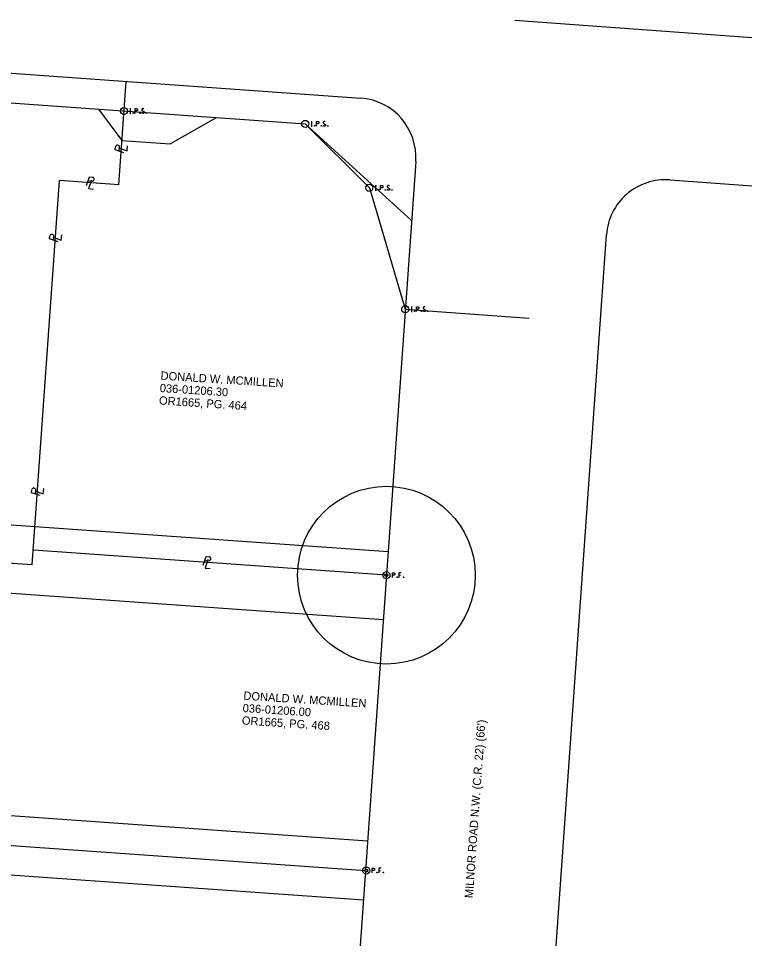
# Model space of a CAD drawing. Extents: x 1898254 to 1901377, y 701554 to 704886.
# Drawn here: x 1899648.1 to 1899893.4, y 702919.7 to 703230.4 of the extents above; entities that cross this region are included whole.
import ezdxf

# ---------------------------------------------------------------- set-up
doc = ezdxf.new("R2010")
doc.units = 0
for name, color, linetype in [('_CIVIL_CONSTRUCTION', 7, 'Continuous'), ('DV_X_Property_Line', 7, 'Continuous'), ('DV_X_Text', 7, 'Continuous'), ('PF_X_Ground_Line', 7, 'Continuous'), ('RW_X_CL', 7, 'Continuous'), ('RW_X_Esmt_SW', 7, 'Continuous'), ('RW_X_Esmt_U', 7, 'Continuous'), ('RW_X_Fee_RW', 7, 'Continuous'), ('RW_X_Text', 7, 'Continuous'), ('SC_Scratch1', 7, 'Continuous'), ('SC_Scratch2', 7, 'Continuous'), ('SC_Scratch5', 7, 'Continuous'), ('SG_X_Manhole', 7, 'Continuous'), ('SV_P_Mon_Cells_Set', 7, 'Continuous'), ('SV_X_Mon_Cells_Found', 7, 'Continuous')]:
    doc.layers.add(name, color=color, linetype=linetype)

msp = doc.modelspace()

# ---------------------------------------------------------------- linework, layer by layer
at = {"layer": '_CIVIL_CONSTRUCTION'}
msp.add_lwpolyline([(1899675.17, 703199.74), (1899683.04, 703189.15), (1899699.4, 703187.99), (1899715.07, 703196.9)], dxfattribs=at)
at = {"layer": 'DV_X_Property_Line'}
for p, q in [((1899681.98, 703174.19), (1899684.46, 703209.1)), ((1899682.16, 703185.57), (1899682.25, 703186.87)), ((1899682.84, 703186.33), (1899682.84, 703186.33)), ((1899652.8, 703045.9), (1899662.03, 703175.61)), ((1899681.98, 703174.19), (1899662.03, 703175.61)), ((1899671.67, 703175.55), (1899672.96, 703175.45)), ((1899672.42, 703174.87), (1899672.42, 703174.87)), ((1899659.97, 703155.46), (1899660.06, 703156.75)), ((1899660.65, 703156.21), (1899660.65, 703156.21)), ((1899653.88, 703069.79), (1899653.97, 703071.08)), ((1899654.56, 703070.54), (1899654.56, 703070.54)), ((1899652.8, 703045.9), (1899563.03, 703052.28)), ((1899772.41, 703042.41), (1899653.16, 703050.89)), ((1899711.05, 703047.39), (1899712.34, 703047.3)), ((1899711.8, 703046.72), (1899711.8, 703046.72)), ((1899466.52, 702963.89), (1899765.35, 702942.72))]:
    msp.add_line(p, q, dxfattribs=at)
for points in [[(1899683.72, 703185.04), (1899680.82, 703186.03), (1899680.89, 703187.06)], [(1899681.9, 703186.66), (1899684.8, 703185.66), (1899684.92, 703187.41)], [(1899671.13, 703173.99), (1899672.12, 703176.89), (1899673.16, 703176.82)], [(1899672.76, 703175.81), (1899671.76, 703172.91), (1899673.5, 703172.79)], [(1899661.53, 703154.93), (1899658.63, 703155.92), (1899658.7, 703156.95)], [(1899659.71, 703156.55), (1899662.6, 703155.55), (1899662.73, 703157.29)], [(1899655.44, 703069.26), (1899652.53, 703070.25), (1899652.61, 703071.28)], [(1899653.62, 703070.88), (1899656.51, 703069.88), (1899656.64, 703071.62)], [(1899710.51, 703045.84), (1899711.5, 703048.74), (1899712.53, 703048.66)], [(1899712.14, 703047.65), (1899711.14, 703044.76), (1899712.88, 703044.64)]]:
    msp.add_lwpolyline(points, dxfattribs=at)
for centre, start, end in [((1899681.57, 703186.91), 356.4035, 167.2606), ((1899673, 703176.14), 266.4035, 77.2606), ((1899659.37, 703156.8), 356.4035, 167.2606), ((1899653.28, 703071.13), 356.4035, 167.2606), ((1899712.38, 703047.99), 266.4035, 77.2606)]:
    msp.add_arc(centre, 0.69, start, end, dxfattribs=at)
at = {"layer": 'DV_X_Text'}
msp.add_line((1899778.77, 703132.21), (1899820.67, 703129.24), dxfattribs=at)
at = {"layer": 'PF_X_Ground_Line'}
msp.add_lwpolyline([(1899484.96, 703223.29), (1899484.25, 703213.31), (1899745, 703194.77), (1899766.64, 703173.17), (1899778.77, 703132.21)], dxfattribs=at)
at = {"layer": 'RW_X_CL'}
msp.add_line((1899815.76, 703229.84), (1901162.17, 703131.42), dxfattribs=at)
at = {"layer": 'RW_X_Esmt_SW'}
for p, q in [((1899489.14, 703070.57), (1899772.98, 703050.39)), ((1899492.79, 703047.25), (1899771.35, 703027.44))]:
    msp.add_line(p, q, dxfattribs=at)
at = {"layer": 'RW_X_Esmt_U'}
for points in [[(1899494.94, 703222.58), (1899477.2, 702973.16), (1899766.06, 702952.7)], [(1899550.18, 702947.94), (1899580.04, 702945.82), (1899764.64, 702932.75)]]:
    msp.add_lwpolyline(points, dxfattribs=at)
at = {"layer": 'RW_X_Fee_RW'}
for p, q in [((1898449.4, 703296.93), (1899763.77, 703203.46)), ((1899782.31, 703182.1), (1899756.17, 702813.12)), ((1899868.13, 703175.88), (1900606.62, 703121.9)), ((1899745.58, 701729.7), (1899846.72, 703157.34))]:
    msp.add_line(p, q, dxfattribs=at)
for centre, start, end in [((1899762.36, 703183.51), 355.9478, 85.9325), ((1899866.67, 703155.93), 85.8192, 175.9478)]:
    msp.add_arc(centre, 20, start, end, dxfattribs=at)
at = {"layer": 'SC_Scratch1'}
msp.add_circle((1899772.41, 703042.41), 30, dxfattribs=at)
at = {"layer": 'SC_Scratch2'}
msp.add_circle((1899815.76, 703229.84), 1561.35, dxfattribs=at)
at = {"layer": 'SC_Scratch5'}
for p, q in [((1898449.4, 703296.93), (1899763.77, 703203.46)), ((1899782.31, 703182.1), (1899700.34, 702025)), ((1899868.13, 703175.88), (1900606.62, 703121.9)), ((1899745.58, 701729.7), (1899846.72, 703157.34))]:
    msp.add_line(p, q, dxfattribs=at)
for points in [[(1899484.96, 703223.29), (1899484.25, 703213.31), (1899745, 703194.77), (1899780.89, 703162.13)], [(1899675.17, 703199.74), (1899683.04, 703189.15), (1899699.4, 703187.99), (1899715.07, 703196.9)]]:
    msp.add_lwpolyline(points, dxfattribs=at)
for centre, start, end in [((1899762.36, 703183.51), 355.9478, 85.9325), ((1899866.67, 703155.93), 85.8192, 175.9478)]:
    msp.add_arc(centre, 20, start, end, dxfattribs=at)
at = {"layer": 'SG_X_Manhole'}
for points in [[(1899484.96, 703223.29), (1899484.25, 703213.31), (1899745, 703194.77), (1899780.89, 703162.13)], [(1899484.96, 703223.29), (1899484.25, 703213.31), (1899745, 703194.77), (1899745, 703194.77)]]:
    msp.add_lwpolyline(points, dxfattribs=at)
at = {"layer": 'SV_P_Mon_Cells_Set'}
for points in [[(1899685.77, 703199.93), (1899686.12, 703199.93)], [(1899685.77, 703198.33), (1899686.12, 703198.33)], [(1899685.95, 703198.33), (1899685.95, 703199.93)], [(1899686.91, 703198.54), (1899686.96, 703198.54), (1899686.99, 703198.52), (1899687.03, 703198.47), (1899687.03, 703198.4), (1899686.99, 703198.35), (1899686.96, 703198.33), (1899686.91, 703198.33), (1899686.87, 703198.35), (1899686.84, 703198.4), (1899686.84, 703198.47), (1899686.87, 703198.52), (1899686.91, 703198.54)], [(1899687.51, 703198.33), (1899687.51, 703199.93), (1899688.04, 703199.93), (1899688.1, 703199.91), (1899688.17, 703199.89), (1899688.21, 703199.86), (1899688.24, 703199.84), (1899688.28, 703199.78), (1899688.32, 703199.71), (1899688.34, 703199.61), (1899688.34, 703199.46), (1899688.33, 703199.41), (1899688.31, 703199.33), (1899688.26, 703199.25), (1899688.22, 703199.21), (1899688.18, 703199.18), (1899688.13, 703199.16), (1899688.04, 703199.15), (1899687.51, 703199.15)], [(1899689.15, 703198.54), (1899689.21, 703198.54), (1899689.24, 703198.52), (1899689.28, 703198.47), (1899689.28, 703198.4), (1899689.24, 703198.35), (1899689.21, 703198.33), (1899689.15, 703198.33), (1899689.12, 703198.35), (1899689.09, 703198.4), (1899689.09, 703198.47), (1899689.12, 703198.52), (1899689.15, 703198.54)], [(1899690.52, 703199.81), (1899690.5, 703199.84), (1899690.47, 703199.86), (1899690.37, 703199.9), (1899690.25, 703199.93), (1899690.16, 703199.93), (1899690.12, 703199.93), (1899689.98, 703199.89), (1899689.86, 703199.81), (1899689.78, 703199.71), (1899689.76, 703199.61), (1899689.76, 703199.54), (1899689.78, 703199.44), (1899689.87, 703199.35), (1899690.48, 703198.97), (1899690.53, 703198.92), (1899690.55, 703198.87), (1899690.58, 703198.79), (1899690.58, 703198.72), (1899690.56, 703198.64), (1899690.55, 703198.59), (1899690.53, 703198.53), (1899690.51, 703198.48), (1899690.49, 703198.44), (1899690.45, 703198.4), (1899690.42, 703198.38), (1899690.38, 703198.35), (1899690.34, 703198.34), (1899690.25, 703198.33), (1899690.09, 703198.33), (1899689.99, 703198.35), (1899689.85, 703198.44), (1899689.76, 703198.52)], [(1899691.34, 703198.54), (1899691.39, 703198.54), (1899691.42, 703198.52), (1899691.46, 703198.47), (1899691.46, 703198.4), (1899691.42, 703198.35), (1899691.39, 703198.33), (1899691.34, 703198.33), (1899691.3, 703198.35), (1899691.27, 703198.4), (1899691.27, 703198.47), (1899691.3, 703198.52), (1899691.34, 703198.54)], [(1899747.01, 703195.57), (1899747.37, 703195.57)], [(1899747.19, 703193.97), (1899747.19, 703195.57)], [(1899748.76, 703193.97), (1899748.76, 703195.57), (1899749.28, 703195.57), (1899749.34, 703195.56), (1899749.42, 703195.53), (1899749.45, 703195.51), (1899749.48, 703195.48), (1899749.53, 703195.42), (1899749.56, 703195.36), (1899749.58, 703195.26), (1899749.58, 703195.11), (1899749.57, 703195.06), (1899749.55, 703194.98), (1899749.51, 703194.89), (1899749.46, 703194.85), (1899749.43, 703194.83), (1899749.37, 703194.8), (1899749.28, 703194.79), (1899748.76, 703194.79)], [(1899751.77, 703195.46), (1899751.74, 703195.48), (1899751.71, 703195.51), (1899751.61, 703195.55), (1899751.49, 703195.57), (1899751.4, 703195.57), (1899751.37, 703195.57), (1899751.22, 703195.53), (1899751.1, 703195.46), (1899751.03, 703195.36), (1899751, 703195.26), (1899751, 703195.18), (1899751.03, 703195.08), (1899751.11, 703194.99), (1899751.72, 703194.61), (1899751.78, 703194.56), (1899751.8, 703194.51), (1899751.82, 703194.44), (1899751.82, 703194.36), (1899751.81, 703194.29), (1899751.8, 703194.24), (1899751.78, 703194.17), (1899751.75, 703194.12), (1899751.73, 703194.09), (1899751.7, 703194.05), (1899751.67, 703194.02), (1899751.62, 703194), (1899751.59, 703193.98), (1899751.49, 703193.97), (1899751.34, 703193.97), (1899751.24, 703194), (1899751.09, 703194.09), (1899751, 703194.16)], [(1899747.01, 703193.97), (1899747.37, 703193.97)], [(1899748.15, 703194.19), (1899748.2, 703194.19), (1899748.24, 703194.16), (1899748.27, 703194.11), (1899748.27, 703194.05), (1899748.24, 703194), (1899748.2, 703193.97), (1899748.15, 703193.97), (1899748.12, 703194), (1899748.08, 703194.05), (1899748.08, 703194.11), (1899748.12, 703194.16), (1899748.15, 703194.19)], [(1899750.4, 703194.19), (1899750.45, 703194.19), (1899750.49, 703194.16), (1899750.52, 703194.11), (1899750.52, 703194.05), (1899750.49, 703194), (1899750.45, 703193.97), (1899750.4, 703193.97), (1899750.37, 703194), (1899750.33, 703194.05), (1899750.33, 703194.11), (1899750.37, 703194.16), (1899750.4, 703194.19)], [(1899752.58, 703194.19), (1899752.64, 703194.19), (1899752.67, 703194.16), (1899752.7, 703194.11), (1899752.7, 703194.05), (1899752.67, 703194), (1899752.64, 703193.97), (1899752.58, 703193.97), (1899752.55, 703194), (1899752.51, 703194.05), (1899752.51, 703194.11), (1899752.55, 703194.16), (1899752.58, 703194.19)], [(1899768.66, 703173.97), (1899769.01, 703173.97)], [(1899768.83, 703172.37), (1899768.83, 703173.97)], [(1899770.4, 703172.37), (1899770.4, 703173.97), (1899770.93, 703173.97), (1899770.98, 703173.96), (1899771.06, 703173.93), (1899771.09, 703173.91), (1899771.12, 703173.88), (1899771.17, 703173.82), (1899771.2, 703173.76), (1899771.22, 703173.66), (1899771.22, 703173.5), (1899771.21, 703173.45), (1899771.19, 703173.38), (1899771.15, 703173.29), (1899771.1, 703173.25), (1899771.07, 703173.23), (1899771.01, 703173.2), (1899770.93, 703173.19), (1899770.4, 703173.19)], [(1899773.41, 703173.86), (1899773.38, 703173.88), (1899773.35, 703173.91), (1899773.25, 703173.95), (1899773.13, 703173.97), (1899773.04, 703173.97), (1899773.01, 703173.97), (1899772.87, 703173.93), (1899772.75, 703173.86), (1899772.67, 703173.76), (1899772.65, 703173.66), (1899772.65, 703173.58), (1899772.67, 703173.48), (1899772.76, 703173.39), (1899773.36, 703173.01), (1899773.42, 703172.96), (1899773.44, 703172.91), (1899773.46, 703172.84), (1899773.46, 703172.76), (1899773.45, 703172.69), (1899773.44, 703172.64), (1899773.42, 703172.57), (1899773.4, 703172.52), (1899773.37, 703172.48), (1899773.34, 703172.45), (1899773.31, 703172.42), (1899773.26, 703172.4), (1899773.23, 703172.38), (1899773.13, 703172.37), (1899772.98, 703172.37), (1899772.88, 703172.4), (1899772.73, 703172.48), (1899772.65, 703172.56)], [(1899768.66, 703172.37), (1899769.01, 703172.37)], [(1899769.79, 703172.58), (1899769.85, 703172.58), (1899769.88, 703172.56), (1899769.91, 703172.51), (1899769.91, 703172.45), (1899769.88, 703172.4), (1899769.85, 703172.37), (1899769.79, 703172.37), (1899769.76, 703172.4), (1899769.72, 703172.45), (1899769.72, 703172.51), (1899769.76, 703172.56), (1899769.79, 703172.58)], [(1899772.04, 703172.58), (1899772.09, 703172.58), (1899772.13, 703172.56), (1899772.16, 703172.51), (1899772.16, 703172.45), (1899772.13, 703172.4), (1899772.09, 703172.37), (1899772.04, 703172.37), (1899772.01, 703172.4), (1899771.97, 703172.45), (1899771.97, 703172.51), (1899772.01, 703172.56), (1899772.04, 703172.58)], [(1899774.22, 703172.58), (1899774.28, 703172.58), (1899774.31, 703172.56), (1899774.34, 703172.51), (1899774.34, 703172.45), (1899774.31, 703172.4), (1899774.28, 703172.37), (1899774.22, 703172.37), (1899774.19, 703172.4), (1899774.16, 703172.45), (1899774.16, 703172.51), (1899774.19, 703172.56), (1899774.22, 703172.58)], [(1899780.79, 703133.01), (1899781.14, 703133.01)], [(1899780.97, 703131.41), (1899780.97, 703133.01)], [(1899782.53, 703131.41), (1899782.53, 703133.01), (1899783.06, 703133.01), (1899783.12, 703133), (1899783.19, 703132.97), (1899783.23, 703132.95), (1899783.26, 703132.92), (1899783.3, 703132.86), (1899783.34, 703132.8), (1899783.36, 703132.7), (1899783.36, 703132.54), (1899783.35, 703132.49), (1899783.33, 703132.42), (1899783.28, 703132.33), (1899783.24, 703132.29), (1899783.21, 703132.27), (1899783.15, 703132.24), (1899783.06, 703132.23), (1899782.53, 703132.23)], [(1899785.54, 703132.9), (1899785.52, 703132.92), (1899785.49, 703132.95), (1899785.39, 703132.99), (1899785.27, 703133.01), (1899785.18, 703133.01), (1899785.15, 703133.01), (1899785, 703132.97), (1899784.88, 703132.9), (1899784.8, 703132.8), (1899784.78, 703132.7), (1899784.78, 703132.62), (1899784.8, 703132.52), (1899784.89, 703132.43), (1899785.5, 703132.05), (1899785.55, 703132), (1899785.57, 703131.95), (1899785.6, 703131.88), (1899785.6, 703131.8), (1899785.59, 703131.73), (1899785.57, 703131.68), (1899785.55, 703131.61), (1899785.53, 703131.56), (1899785.51, 703131.52), (1899785.48, 703131.49), (1899785.44, 703131.46), (1899785.4, 703131.44), (1899785.37, 703131.42), (1899785.27, 703131.41), (1899785.11, 703131.41), (1899785.01, 703131.44), (1899784.87, 703131.52), (1899784.78, 703131.6)], [(1899780.79, 703131.41), (1899781.14, 703131.41)], [(1899781.93, 703131.62), (1899781.98, 703131.62), (1899782.01, 703131.6), (1899782.05, 703131.55), (1899782.05, 703131.49), (1899782.01, 703131.44), (1899781.98, 703131.41), (1899781.93, 703131.41), (1899781.89, 703131.44), (1899781.86, 703131.49), (1899781.86, 703131.55), (1899781.89, 703131.6), (1899781.93, 703131.62)], [(1899784.18, 703131.62), (1899784.23, 703131.62), (1899784.26, 703131.6), (1899784.3, 703131.55), (1899784.3, 703131.49), (1899784.26, 703131.44), (1899784.23, 703131.41), (1899784.18, 703131.41), (1899784.14, 703131.44), (1899784.11, 703131.49), (1899784.11, 703131.55), (1899784.14, 703131.6), (1899784.18, 703131.62)], [(1899786.36, 703131.62), (1899786.41, 703131.62), (1899786.45, 703131.6), (1899786.48, 703131.55), (1899786.48, 703131.49), (1899786.45, 703131.44), (1899786.41, 703131.41), (1899786.36, 703131.41), (1899786.32, 703131.44), (1899786.29, 703131.49), (1899786.29, 703131.55), (1899786.32, 703131.6), (1899786.36, 703131.62)]]:
    msp.add_lwpolyline(points, dxfattribs=at)
for centre in [(1899683.75, 703199.13), (1899745, 703194.77), (1899766.64, 703173.17), (1899778.77, 703132.21)]:
    msp.add_circle(centre, 1.2, dxfattribs=at)
at = {"layer": 'SV_X_Mon_Cells_Found'}
for points in [[(1899774.41, 703041.61), (1899774.41, 703043.21), (1899774.94, 703043.21), (1899774.99, 703043.19), (1899775.07, 703043.17), (1899775.1, 703043.14), (1899775.13, 703043.12), (1899775.18, 703043.05), (1899775.21, 703042.99), (1899775.23, 703042.89), (1899775.23, 703042.74), (1899775.22, 703042.69), (1899775.2, 703042.61), (1899775.16, 703042.53), (1899775.11, 703042.49), (1899775.08, 703042.46), (1899775.02, 703042.44), (1899774.94, 703042.42), (1899774.41, 703042.42)], [(1899777.42, 703043.21), (1899776.66, 703043.21), (1899776.66, 703041.61)], [(1899776.05, 703041.82), (1899776.1, 703041.82), (1899776.14, 703041.8), (1899776.17, 703041.74), (1899776.17, 703041.68), (1899776.14, 703041.63), (1899776.1, 703041.61), (1899776.05, 703041.61), (1899776.02, 703041.63), (1899775.98, 703041.68), (1899775.98, 703041.74), (1899776.02, 703041.8), (1899776.05, 703041.82)], [(1899776.66, 703042.42), (1899777.2, 703042.42)], [(1899778.2, 703041.82), (1899778.25, 703041.82), (1899778.29, 703041.8), (1899778.32, 703041.74), (1899778.32, 703041.68), (1899778.29, 703041.63), (1899778.25, 703041.61), (1899778.2, 703041.61), (1899778.17, 703041.63), (1899778.13, 703041.68), (1899778.13, 703041.74), (1899778.17, 703041.8), (1899778.2, 703041.82)], [(1899767.59, 702941.91), (1899767.59, 702943.51), (1899768.12, 702943.51), (1899768.18, 702943.49), (1899768.25, 702943.47), (1899768.29, 702943.44), (1899768.32, 702943.42), (1899768.36, 702943.35), (1899768.4, 702943.29), (1899768.42, 702943.19), (1899768.42, 702943.04), (1899768.41, 702942.99), (1899768.39, 702942.91), (1899768.34, 702942.83), (1899768.3, 702942.79), (1899768.27, 702942.76), (1899768.21, 702942.74), (1899768.12, 702942.72), (1899767.59, 702942.72)], [(1899770.6, 702943.51), (1899769.84, 702943.51), (1899769.84, 702941.91)], [(1899769.24, 702942.12), (1899769.29, 702942.12), (1899769.32, 702942.09), (1899769.36, 702942.04), (1899769.36, 702941.98), (1899769.32, 702941.93), (1899769.29, 702941.91), (1899769.24, 702941.91), (1899769.2, 702941.93), (1899769.17, 702941.98), (1899769.17, 702942.04), (1899769.2, 702942.09), (1899769.24, 702942.12)], [(1899769.84, 702942.72), (1899770.38, 702942.72)], [(1899771.38, 702942.12), (1899771.44, 702942.12), (1899771.47, 702942.09), (1899771.51, 702942.04), (1899771.51, 702941.98), (1899771.47, 702941.93), (1899771.44, 702941.91), (1899771.38, 702941.91), (1899771.35, 702941.93), (1899771.32, 702941.98), (1899771.32, 702942.04), (1899771.35, 702942.09), (1899771.38, 702942.12)]]:
    msp.add_lwpolyline(points, dxfattribs=at)
for centre, radius in [((1899772.41, 703042.41), 1.2), ((1899772.41, 703042.41), 0.495), ((1899765.6, 702942.71), 1.2), ((1899765.6, 702942.71), 0.495)]:
    msp.add_circle(centre, radius, dxfattribs=at)

# ---------------------------------------------------------------- texts
at = {"layer": 'DV_X_Text'}
for s, p in [('DONALD W. MCMILLEN', (1899696.06, 703108.44)), ('036-01206.30', (1899695.79, 703104.25)), ('OR1665, PG. 464', (1899695.53, 703100.05)), ('DONALD W. MCMILLEN', (1899724.04, 703000.39)), ('036-01206.00', (1899723.78, 702996.2)), ('OR1665, PG. 468', (1899723.51, 702992.01))]:
    msp.add_text(s, height=2.8, rotation=356.3351, dxfattribs=at).set_placement(p)
at = {"layer": 'RW_X_Text'}
msp.add_text("MILNOR ROAD N.W. (C.R. 22) (66')", height=2.8, rotation=85.9325, dxfattribs=at).set_placement((1899801.62, 702933.28))

doc.saveas('drawing.dxf')
